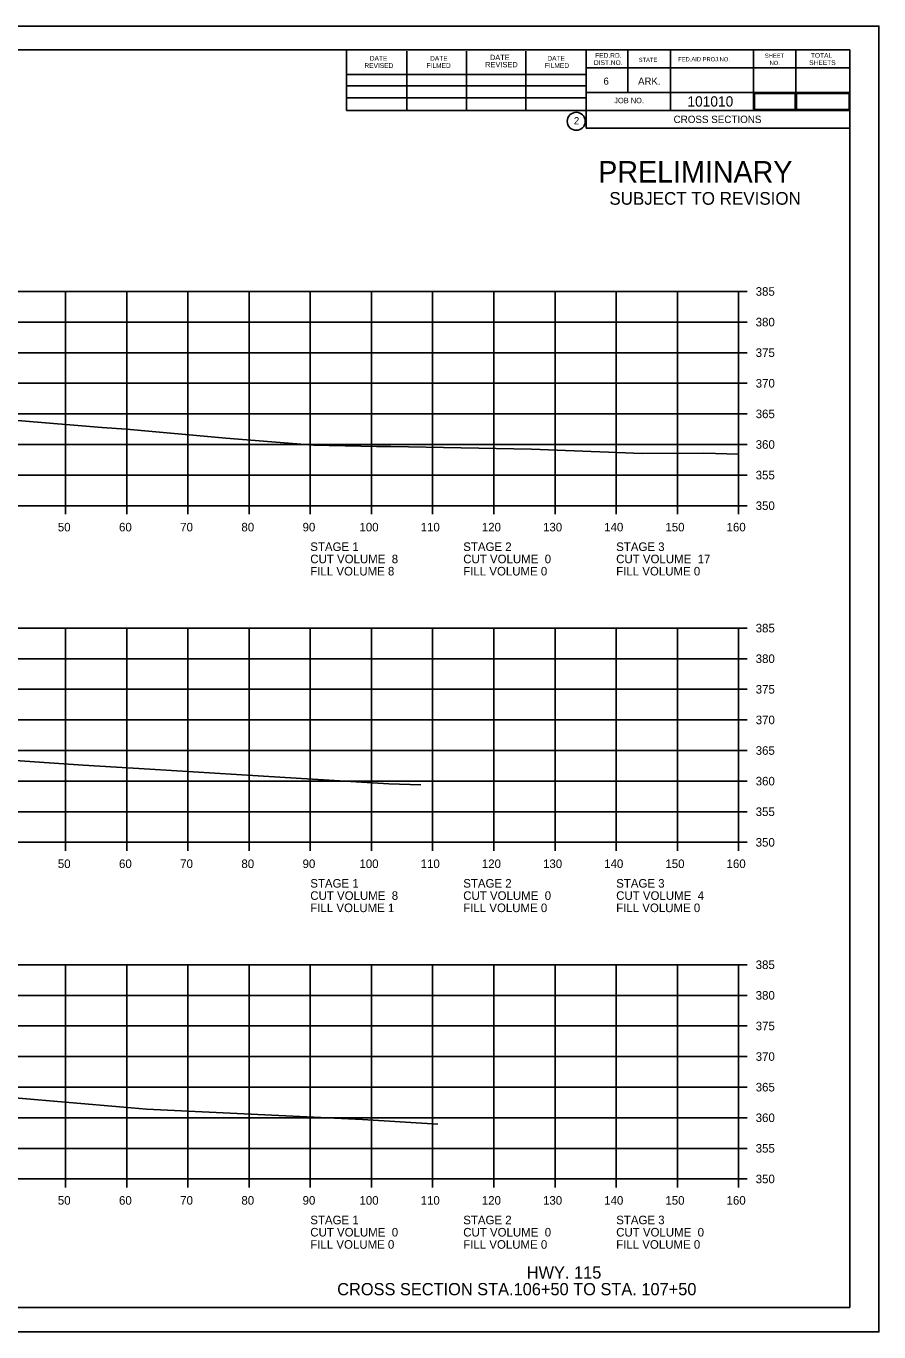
# Model space of a CAD drawing. Extents: x 1630712 to 1632516, y 782146 to 785403.
# Drawn here: x 1632376.5 to 1632515.9, y 783483.3 to 783696.6 of the extents above; entities that cross this region are included whole.
import ezdxf

# ---------------------------------------------------------------- set-up
doc = ezdxf.new("R2010")
doc.units = 0
for name, color, linetype in [('Page Number', 7, 'Continuous'), ('R_Axis', 7, 'Continuous'), ('R_Axis Annot', 7, 'Continuous'), ('R_Border', 7, 'Continuous'), ('R_Border Notes', 7, 'Continuous'), ('R_Border Prem', 7, 'Continuous'), ('R_Draft', 7, 'Continuous'), ('R_Exist Surface', 7, 'Continuous'), ('R_Grid', 7, 'Continuous'), ('R_No Plot', 7, 'Continuous'), ('Total_Pages', 7, 'Continuous')]:
    doc.layers.add(name, color=color, linetype=linetype)

msp = doc.modelspace()

# ---------------------------------------------------------------- linework, layer by layer
at = {"layer": 'Page Number'}
msp.add_lwpolyline([(1632495.54, 783683.01), (1632502.21, 783683.01), (1632502.21, 783685.65), (1632495.54, 783685.65)], close=True, dxfattribs=at)
at = {"layer": 'R_Axis'}
for p, q in [((1632492.96, 783618.28), (1632492.96, 783653.28)), ((1632494.36, 783653.28), (1632492.96, 783653.28)), ((1632494.36, 783648.28), (1632492.96, 783648.28)), ((1632494.36, 783643.28), (1632492.96, 783643.28)), ((1632494.36, 783638.28), (1632492.96, 783638.28)), ((1632494.36, 783633.28), (1632492.96, 783633.28)), ((1632494.36, 783628.28), (1632492.96, 783628.28)), ((1632494.36, 783623.28), (1632492.96, 783623.28)), ((1632212.96, 783618.28), (1632492.96, 783618.28)), ((1632382.96, 783616.88), (1632382.96, 783618.28)), ((1632392.96, 783616.88), (1632392.96, 783618.28)), ((1632402.96, 783616.88), (1632402.96, 783618.28)), ((1632412.96, 783616.88), (1632412.96, 783618.28)), ((1632422.96, 783616.88), (1632422.96, 783618.28)), ((1632432.96, 783616.88), (1632432.96, 783618.28)), ((1632442.96, 783616.88), (1632442.96, 783618.28)), ((1632452.96, 783616.88), (1632452.96, 783618.28)), ((1632462.96, 783616.88), (1632462.96, 783618.28)), ((1632472.96, 783616.88), (1632472.96, 783618.28)), ((1632482.96, 783616.88), (1632482.96, 783618.28)), ((1632492.96, 783616.88), (1632492.96, 783618.28)), ((1632494.36, 783618.28), (1632492.96, 783618.28)), ((1632492.96, 783563.28), (1632492.96, 783598.28)), ((1632494.36, 783598.28), (1632492.96, 783598.28)), ((1632494.36, 783593.28), (1632492.96, 783593.28)), ((1632494.36, 783588.28), (1632492.96, 783588.28)), ((1632494.36, 783583.28), (1632492.96, 783583.28)), ((1632494.36, 783578.28), (1632492.96, 783578.28)), ((1632494.36, 783573.28), (1632492.96, 783573.28)), ((1632494.36, 783568.28), (1632492.96, 783568.28)), ((1632212.96, 783563.28), (1632492.96, 783563.28)), ((1632382.96, 783561.88), (1632382.96, 783563.28)), ((1632392.96, 783561.88), (1632392.96, 783563.28)), ((1632402.96, 783561.88), (1632402.96, 783563.28)), ((1632412.96, 783561.88), (1632412.96, 783563.28)), ((1632422.96, 783561.88), (1632422.96, 783563.28)), ((1632432.96, 783561.88), (1632432.96, 783563.28)), ((1632442.96, 783561.88), (1632442.96, 783563.28)), ((1632452.96, 783561.88), (1632452.96, 783563.28)), ((1632462.96, 783561.88), (1632462.96, 783563.28)), ((1632472.96, 783561.88), (1632472.96, 783563.28)), ((1632482.96, 783561.88), (1632482.96, 783563.28)), ((1632492.96, 783561.88), (1632492.96, 783563.28)), ((1632494.36, 783563.28), (1632492.96, 783563.28)), ((1632492.96, 783508.28), (1632492.96, 783543.28)), ((1632494.36, 783543.28), (1632492.96, 783543.28)), ((1632494.36, 783538.28), (1632492.96, 783538.28)), ((1632494.36, 783533.28), (1632492.96, 783533.28)), ((1632494.36, 783528.28), (1632492.96, 783528.28)), ((1632494.36, 783523.28), (1632492.96, 783523.28)), ((1632494.36, 783518.28), (1632492.96, 783518.28)), ((1632494.36, 783513.28), (1632492.96, 783513.28)), ((1632212.96, 783508.28), (1632492.96, 783508.28)), ((1632382.96, 783506.88), (1632382.96, 783508.28)), ((1632392.96, 783506.88), (1632392.96, 783508.28)), ((1632402.96, 783506.88), (1632402.96, 783508.28)), ((1632412.96, 783506.88), (1632412.96, 783508.28)), ((1632422.96, 783506.88), (1632422.96, 783508.28)), ((1632432.96, 783506.88), (1632432.96, 783508.28)), ((1632442.96, 783506.88), (1632442.96, 783508.28)), ((1632452.96, 783506.88), (1632452.96, 783508.28)), ((1632462.96, 783506.88), (1632462.96, 783508.28)), ((1632472.96, 783506.88), (1632472.96, 783508.28)), ((1632482.96, 783506.88), (1632482.96, 783508.28)), ((1632492.96, 783506.88), (1632492.96, 783508.28)), ((1632494.36, 783508.28), (1632492.96, 783508.28))]:
    msp.add_line(p, q, dxfattribs=at)
at = {"layer": 'R_Border'}
for p, q in [((1632194.96, 783692.74), (1632511.14, 783692.74)), ((1632428.88, 783682.86), (1632428.88, 783692.74)), ((1632438.74, 783682.86), (1632438.74, 783692.54)), ((1632448.5, 783682.86), (1632448.5, 783692.54)), ((1632458.18, 783682.86), (1632458.18, 783692.54)), ((1632468.04, 783692.74), (1632468.04, 783679.94)), ((1632474.88, 783692.74), (1632474.88, 783685.8)), ((1632481.82, 783692.74), (1632481.82, 783682.86)), ((1632495.4, 783692.74), (1632495.4, 783682.86)), ((1632502.34, 783692.74), (1632502.34, 783682.86)), ((1632511.14, 783487.28), (1632511.14, 783692.74)), ((1632511.14, 783689.8), (1632468.04, 783689.8)), ((1632511.14, 783689.82), (1632511.14, 783689.82)), ((1632428.88, 783688.72), (1632468.04, 783688.72)), ((1632428.88, 783686.86), (1632468.04, 783686.86)), ((1632511.14, 783685.8), (1632468.04, 783685.8)), ((1632471, 783685.8), (1632511.14, 783685.8)), ((1632428.88, 783682.86), (1632428.88, 783684.92)), ((1632428.88, 783684.92), (1632468.04, 783684.92)), ((1632511.14, 783682.86), (1632428.88, 783682.86)), ((1632468.04, 783679.94), (1632511.14, 783679.94)), ((1632511.14, 783487.28), (1632194.96, 783487.28))]:
    msp.add_line(p, q, dxfattribs=at)
msp.add_circle((1632466.43, 783681.08), 1.47, dxfattribs=at)
at = {"layer": 'R_Exist Surface'}
for points in [[(1632375.08, 783632.19), (1632388.88, 783631.07), (1632392.91, 783630.76), (1632409.18, 783629.34), (1632423.47, 783628.17), (1632433.78, 783627.94), (1632436.13, 783627.95), (1632459.12, 783627.54), (1632477.28, 783626.79), (1632487.31, 783626.88), (1632492.96, 783626.69)], [(1632374.73, 783576.63), (1632385.82, 783575.91), (1632396.76, 783575.24), (1632417.98, 783573.93), (1632435.8, 783572.83), (1632441.01, 783572.65)], [(1632374.68, 783521.56), (1632392.43, 783519.99), (1632396.17, 783519.68), (1632431.49, 783517.99), (1632443.79, 783517.26)]]:
    msp.add_lwpolyline(points, dxfattribs=at)
at = {"layer": 'R_Grid'}
for p, q in [((1632212.96, 783653.28), (1632492.96, 783653.28)), ((1632382.96, 783618.28), (1632382.96, 783653.28)), ((1632392.96, 783618.28), (1632392.96, 783653.28)), ((1632402.96, 783618.28), (1632402.96, 783653.28)), ((1632412.96, 783618.28), (1632412.96, 783653.28)), ((1632422.96, 783618.28), (1632422.96, 783653.28)), ((1632432.96, 783618.28), (1632432.96, 783653.28)), ((1632442.96, 783618.28), (1632442.96, 783653.28)), ((1632452.96, 783618.28), (1632452.96, 783653.28)), ((1632462.96, 783618.28), (1632462.96, 783653.28)), ((1632472.96, 783618.28), (1632472.96, 783653.28)), ((1632482.96, 783618.28), (1632482.96, 783653.28)), ((1632492.96, 783618.28), (1632492.96, 783653.28)), ((1632212.96, 783648.28), (1632492.96, 783648.28)), ((1632212.96, 783643.28), (1632492.96, 783643.28)), ((1632212.96, 783638.28), (1632492.96, 783638.28)), ((1632212.96, 783633.28), (1632492.96, 783633.28)), ((1632212.96, 783628.28), (1632492.96, 783628.28)), ((1632212.96, 783623.28), (1632492.96, 783623.28)), ((1632212.96, 783618.28), (1632492.96, 783618.28)), ((1632212.96, 783598.28), (1632492.96, 783598.28)), ((1632382.96, 783563.28), (1632382.96, 783598.28)), ((1632392.96, 783563.28), (1632392.96, 783598.28)), ((1632402.96, 783563.28), (1632402.96, 783598.28)), ((1632412.96, 783563.28), (1632412.96, 783598.28)), ((1632422.96, 783563.28), (1632422.96, 783598.28)), ((1632432.96, 783563.28), (1632432.96, 783598.28)), ((1632442.96, 783563.28), (1632442.96, 783598.28)), ((1632452.96, 783563.28), (1632452.96, 783598.28)), ((1632462.96, 783563.28), (1632462.96, 783598.28)), ((1632472.96, 783563.28), (1632472.96, 783598.28)), ((1632482.96, 783563.28), (1632482.96, 783598.28)), ((1632492.96, 783563.28), (1632492.96, 783598.28)), ((1632212.96, 783593.28), (1632492.96, 783593.28)), ((1632212.96, 783588.28), (1632492.96, 783588.28)), ((1632212.96, 783583.28), (1632492.96, 783583.28)), ((1632212.96, 783578.28), (1632492.96, 783578.28)), ((1632212.96, 783573.28), (1632492.96, 783573.28)), ((1632212.96, 783568.28), (1632492.96, 783568.28)), ((1632212.96, 783563.28), (1632492.96, 783563.28)), ((1632212.96, 783543.28), (1632492.96, 783543.28)), ((1632382.96, 783508.28), (1632382.96, 783543.28)), ((1632392.96, 783508.28), (1632392.96, 783543.28)), ((1632402.96, 783508.28), (1632402.96, 783543.28)), ((1632412.96, 783508.28), (1632412.96, 783543.28)), ((1632422.96, 783508.28), (1632422.96, 783543.28)), ((1632432.96, 783508.28), (1632432.96, 783543.28)), ((1632442.96, 783508.28), (1632442.96, 783543.28)), ((1632452.96, 783508.28), (1632452.96, 783543.28)), ((1632462.96, 783508.28), (1632462.96, 783543.28)), ((1632472.96, 783508.28), (1632472.96, 783543.28)), ((1632482.96, 783508.28), (1632482.96, 783543.28)), ((1632492.96, 783508.28), (1632492.96, 783543.28)), ((1632212.96, 783538.28), (1632492.96, 783538.28)), ((1632212.96, 783533.28), (1632492.96, 783533.28)), ((1632212.96, 783528.28), (1632492.96, 783528.28)), ((1632212.96, 783523.28), (1632492.96, 783523.28)), ((1632212.96, 783518.28), (1632492.96, 783518.28)), ((1632212.96, 783513.28), (1632492.96, 783513.28)), ((1632212.96, 783508.28), (1632492.96, 783508.28))]:
    msp.add_line(p, q, dxfattribs=at)
at = {"layer": 'R_No Plot'}
for p, q in [((1632182.56, 783696.63), (1632515.9, 783696.63)), ((1632182.56, 783483.3), (1632515.9, 783483.3))]:
    msp.add_line(p, q, dxfattribs=at)
msp.add_lwpolyline([(1632182.56, 783696.63), (1632515.9, 783696.63), (1632515.9, 783483.3), (1632182.56, 783483.3)], close=True, dxfattribs=at)
at = {"layer": 'Total_Pages'}
msp.add_lwpolyline([(1632502.44, 783683.01), (1632511.05, 783683.01), (1632511.05, 783685.65), (1632502.44, 783685.65)], close=True, dxfattribs=at)

# ---------------------------------------------------------------- texts
at = {"layer": 'R_Axis Annot'}
for s, p in [('385', (1632495.76, 783652.58)), ('380', (1632495.76, 783647.58)), ('375', (1632495.76, 783642.58)), ('370', (1632495.76, 783637.58)), ('365', (1632495.76, 783632.58)), ('360', (1632495.76, 783627.58)), ('355', (1632495.76, 783622.58)), ('350', (1632495.76, 783617.58)), ('50', (1632381.7, 783614.08)), ('60', (1632391.7, 783614.08)), ('70', (1632401.7, 783614.08)), ('80', (1632411.7, 783614.08)), ('90', (1632421.7, 783614.08)), ('100', (1632431, 783614.08)), ('110', (1632441, 783614.08)), ('120', (1632451, 783614.08)), ('130', (1632461, 783614.08)), ('140', (1632471, 783614.08)), ('150', (1632481, 783614.08)), ('160', (1632491, 783614.08)), ('STAGE 1', (1632422.96, 783610.88)), ('STAGE 2', (1632447.96, 783610.88)), ('STAGE 3', (1632472.96, 783610.88)), ('CUT VOLUME  8', (1632422.96, 783608.88)), ('FILL VOLUME 8', (1632422.96, 783606.88)), ('CUT VOLUME  0', (1632447.96, 783608.88)), ('FILL VOLUME 0', (1632447.96, 783606.88)), ('CUT VOLUME  17', (1632472.96, 783608.88)), ('FILL VOLUME 0', (1632472.96, 783606.88)), ('385', (1632495.76, 783597.58)), ('380', (1632495.76, 783592.58)), ('375', (1632495.76, 783587.58)), ('370', (1632495.76, 783582.58)), ('365', (1632495.76, 783577.58)), ('360', (1632495.76, 783572.58)), ('355', (1632495.76, 783567.58)), ('350', (1632495.76, 783562.58)), ('50', (1632381.7, 783559.08)), ('60', (1632391.7, 783559.08)), ('70', (1632401.7, 783559.08)), ('80', (1632411.7, 783559.08)), ('90', (1632421.7, 783559.08)), ('100', (1632431, 783559.08)), ('110', (1632441, 783559.08)), ('120', (1632451, 783559.08)), ('130', (1632461, 783559.08)), ('140', (1632471, 783559.08)), ('150', (1632481, 783559.08)), ('160', (1632491, 783559.08)), ('STAGE 1', (1632422.96, 783555.88)), ('STAGE 2', (1632447.96, 783555.88)), ('STAGE 3', (1632472.96, 783555.88)), ('CUT VOLUME  8', (1632422.96, 783553.88)), ('CUT VOLUME  0', (1632447.96, 783553.88)), ('CUT VOLUME  4', (1632472.96, 783553.88)), ('FILL VOLUME 1', (1632422.96, 783551.88)), ('FILL VOLUME 0', (1632447.96, 783551.88)), ('FILL VOLUME 0', (1632472.96, 783551.88)), ('385', (1632495.76, 783542.58)), ('380', (1632495.76, 783537.58)), ('375', (1632495.76, 783532.58)), ('370', (1632495.76, 783527.58)), ('365', (1632495.76, 783522.58)), ('360', (1632495.76, 783517.58)), ('355', (1632495.76, 783512.58)), ('350', (1632495.76, 783507.58)), ('50', (1632381.7, 783504.08)), ('60', (1632391.7, 783504.08)), ('70', (1632401.7, 783504.08)), ('80', (1632411.7, 783504.08)), ('90', (1632421.7, 783504.08)), ('100', (1632431, 783504.08)), ('110', (1632441, 783504.08)), ('120', (1632451, 783504.08)), ('130', (1632461, 783504.08)), ('140', (1632471, 783504.08)), ('150', (1632481, 783504.08)), ('160', (1632491, 783504.08)), ('STAGE 1', (1632422.96, 783500.88)), ('STAGE 2', (1632447.96, 783500.88)), ('STAGE 3', (1632472.96, 783500.88)), ('CUT VOLUME  0', (1632422.96, 783498.88)), ('CUT VOLUME  0', (1632447.96, 783498.88)), ('CUT VOLUME  0', (1632472.96, 783498.88)), ('FILL VOLUME 0', (1632422.96, 783496.88)), ('FILL VOLUME 0', (1632447.96, 783496.88)), ('FILL VOLUME 0', (1632472.96, 783496.88))]:
    msp.add_text(s, height=1.4, dxfattribs=at).set_placement(p)
at = {"layer": 'R_Border'}
for s, height, p in [('DATE', 0.782, (1632432.68, 783690.98)), ('DATE', 0.782, (1632442.54, 783690.98)), ('DATE', 0.879, (1632452.32, 783691.08)), ('DATE', 0.782, (1632461.7, 783690.98)), ('FED.RD.', 0.782, (1632469.52, 783691.46)), ('STATE', 0.684, (1632476.64, 783690.78)), ('FED.AID PROJ.NO.', 0.684, (1632483.1, 783690.88)), ('SHEET', 0.684, (1632497.26, 783691.46)), ('TOTAL', 0.782, (1632504.78, 783691.46)), ('REVISED', 0.782, (1632431.8, 783689.8)), ('FILMED', 0.782, (1632441.96, 783689.8)), ('REVISED', 0.879, (1632451.54, 783689.9)), ('FILMED', 0.782, (1632461.3, 783689.8)), ('DIST.NO.', 0.782, (1632469.32, 783690.28)), ('NO.', 0.684, (1632498.04, 783690.28)), ('SHEETS', 0.782, (1632504.5, 783690.28)), ('6', 1.17, (1632470.88, 783687.06)), ('ARK.', 1.172, (1632476.54, 783687.06)), ('JOB NO.', 0.879, (1632472.64, 783684.04)), ('2', 1.17, (1632466.05, 783680.59))]:
    msp.add_text(s, height=height, rotation=360, dxfattribs=at).set_placement(p)
at = {"layer": 'R_Border Notes'}
for s, height, p in [('101010', 1.68, (1632484.6, 783683.49)), ('CROSS SECTIONS', 1.2, (1632482.34, 783680.8))]:
    msp.add_text(s, height=height, dxfattribs=at).set_placement(p)
at = {"layer": 'R_Border Prem'}
for s, height, p in [('PRELIMINARY', 3.5, (1632470.03, 783671.08)), ('SUBJECT TO REVISION', 2.0751, (1632471.84, 783667.45))]:
    msp.add_text(s, height=height, rotation=360, dxfattribs=at).set_placement(p)
at = {"layer": 'R_Draft'}
for s, p in [('HWY. 115', (1632458.34, 783491.99)), ('CROSS SECTION STA.106+50 TO STA. 107+50', (1632427.36, 783489.28))]:
    msp.add_text(s, height=2, dxfattribs=at).set_placement(p)

doc.saveas('drawing.dxf')
